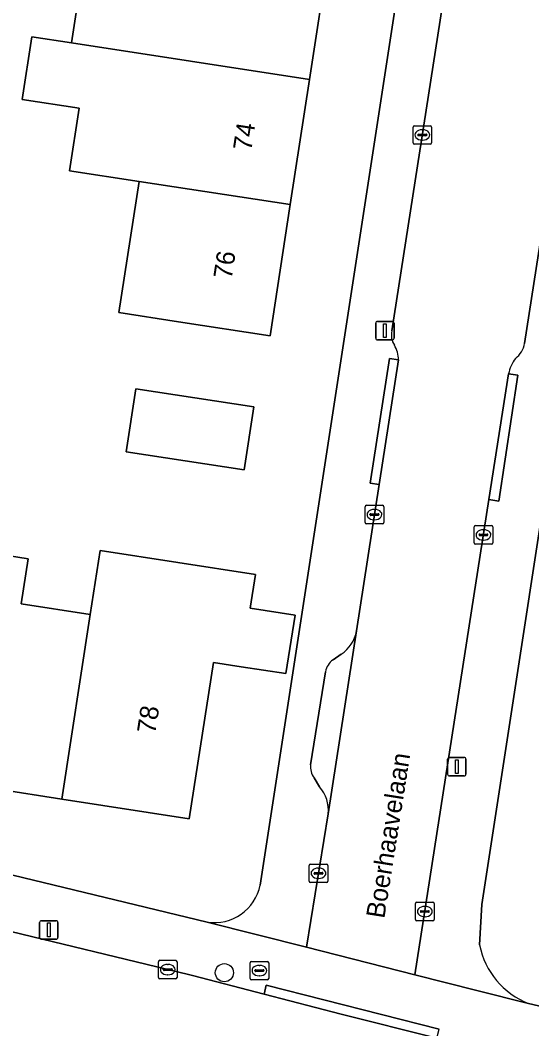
# Model space of a CAD drawing. Extents: x 161483 to 162250, y 379484 to 380833.
# Drawn here: x 161970 to 161997.6, y 380393.9 to 380448.4 of the extents above; entities that cross this region are included whole.
import ezdxf

# ---------------------------------------------------------------- set-up
doc = ezdxf.new("R2010")
doc.units = 0
for name, color, linetype in [('IMGEO_Boom', 7, 'Continuous'), ('IMGEO_Brandkraan', 7, 'Continuous'), ('IMGEO_Erf', 7, 'Continuous'), ('IMGEO_Kolk', 7, 'Continuous'), ('IMGEO_Lichtmast', 7, 'Continuous'), ('IMGEO_Openbare_ruimte_label', 7, 'Continuous'), ('IMGEO_Pand', 7, 'Continuous'), ('IMGEO_Pand_nummerreeks', 7, 'Continuous'), ('IMGEO_Parkeervlak_open', 7, 'Continuous'), ('IMGEO_Rijbaan_lokaal_open', 7, 'Continuous'), ('IMGEO_Voetpad_open', 7, 'Continuous')]:
    doc.layers.add(name, color=color, linetype=linetype)

msp = doc.modelspace()

# ---------------------------------------------------------------- linework, layer by layer
at = {"layer": 'IMGEO_Boom'}
msp.add_circle((161980.989, 380396.97), 0.489, dxfattribs=at)
at = {"layer": 'IMGEO_Brandkraan'}
for p, q in [((161982.38, 380396.657), (161982.38, 380397.509)), ((161982.455, 380397.583), (161983.307, 380397.583)), ((161983.381, 380397.509), (161983.381, 380396.657)), ((161982.639, 380397.077), (161982.639, 380397.089)), ((161983.077, 380397.04), (161982.679, 380397.04)), ((161982.682, 380397.126), (161983.08, 380397.126)), ((161982.868, 380397.363), (161982.893, 380397.363)), ((161983.123, 380397.089), (161983.123, 380397.077)), ((161983.307, 380396.583), (161982.455, 380396.583)), ((161982.891, 380396.803), (161982.866, 380396.803))]:
    msp.add_line(p, q, dxfattribs=at)
for points in [[(161982.38, 380396.657), (161982.38, 380397.509)], [(161982.455, 380397.583), (161983.307, 380397.583)], [(161983.381, 380397.509), (161983.381, 380396.657)], [(161983.307, 380396.583), (161982.455, 380396.583)]]:
    msp.add_lwpolyline(points, dxfattribs=at)
for centre, radius, start, end in [((161982.457, 380397.507), 0.0765, 91.552, 178.448), ((161982.457, 380397.507), 0.0765, 91.552, 178.448), ((161983.305, 380397.507), 0.0765, 1.552, 88.448), ((161983.305, 380397.507), 0.0765, 1.552, 88.448), ((161982.679, 380397.086), 0.0403, 85.8775, 175.7526), ((161982.676, 380397.076), 0.0366, 178.938, 274.7102), ((161983.08, 380397.083), 0.043, 264.8664, 352.4533), ((161983.084, 380397.088), 0.0386, 1.7309, 96.639), ((161982.457, 380396.659), 0.0765, 181.552, 268.448), ((161982.457, 380396.659), 0.0765, 181.552, 268.448), ((161983.305, 380396.659), 0.0765, 271.552, 358.448), ((161983.305, 380396.659), 0.0765, 271.552, 358.448)]:
    msp.add_arc(centre, radius, start, end, dxfattribs=at)
for centre, major_axis, ratio, start_param, end_param in [((161982.867, 380397.083), (-0.387, 0.002), 0.722429, 4.712389, 7.853982), ((161982.892, 380397.083), (-0.39, 0.002), 0.717154, 1.570796, 4.712389)]:
    msp.add_ellipse(centre, major_axis=major_axis, ratio=ratio, start_param=start_param, end_param=end_param, dxfattribs=at)
at = {"layer": 'IMGEO_Erf'}
for points in [[(161982.918, 380401.702), (161997.393, 380495.855)], [(161986.642, 380452.095), (161985.583, 380445.183), (161984.547, 380438.423), (161983.461, 380431.341), (161978.519, 380432.098), (161975.296, 380432.592), (161976.382, 380439.675), (161972.627, 380440.25), (161973.145, 380443.63), (161970.08, 380444.1), (161970.598, 380447.48), (161972.74, 380447.152), (161973.799, 380454.063)], [(162000, 380433.985), (161994.885, 380400.652), (161994.764, 380398.467)], [(161917.857, 380414.284), (161947.471, 380407.585), (161980.058, 380399.699)], [(161997.399, 380395.311), (162000, 380394.69), (162043.415, 380384.478), (162054.712, 380382.262)]]:
    msp.add_lwpolyline(points, dxfattribs=at)
for points in [[(161982.582, 380427.507), (161982.061, 380424.107), (161975.686, 380425.085), (161976.208, 380428.484)], [(161982.661, 380418.463), (161982.379, 380416.643), (161984.801, 380416.269), (161984.313, 380413.109), (161981.889, 380413.483), (161980.406, 380413.712), (161979.096, 380405.273), (161972.21, 380406.342), (161965.323, 380407.412), (161966.09, 380412.353), (161967.248, 380419.805), (161970.406, 380419.315), (161970.028, 380416.881), (161973.754, 380416.302), (161974.29, 380419.761)]]:
    msp.add_lwpolyline(points, close=True, dxfattribs=at)
for centre, radius, start, end in [((161980.445, 380402.189), 2.52, 261.1627, 348.8482), ((161998.934, 380399.271), 4.247, 190.9075, 248.8107)]:
    msp.add_arc(centre, radius, start, end, dxfattribs=at)
at = {"layer": 'IMGEO_Kolk'}
for p, q in [((161991.246, 380442.682), (161992.098, 380442.682)), ((161991.171, 380441.756), (161991.171, 380442.608)), ((161991.43, 380442.176), (161991.43, 380442.188)), ((161991.868, 380442.139), (161991.47, 380442.139)), ((161991.473, 380442.225), (161991.871, 380442.225)), ((161991.659, 380442.462), (161991.684, 380442.462)), ((161991.914, 380442.188), (161991.914, 380442.176)), ((161992.172, 380442.608), (161992.172, 380441.756)), ((161992.098, 380441.682), (161991.246, 380441.682)), ((161991.682, 380441.902), (161991.657, 380441.902)), ((161988.587, 380421.269), (161988.587, 380422.121)), ((161988.662, 380422.195), (161989.514, 380422.195)), ((161989.075, 380421.975), (161989.1, 380421.975)), ((161989.588, 380422.121), (161989.588, 380421.269)), ((161988.846, 380421.689), (161988.846, 380421.701)), ((161989.284, 380421.652), (161988.886, 380421.652)), ((161988.889, 380421.738), (161989.287, 380421.738)), ((161989.098, 380421.415), (161989.073, 380421.415)), ((161989.33, 380421.701), (161989.33, 380421.689)), ((161989.514, 380421.195), (161988.662, 380421.195)), ((161994.469, 380420.173), (161994.469, 380421.025)), ((161994.544, 380421.099), (161995.396, 380421.099)), ((161994.957, 380420.879), (161994.982, 380420.879)), ((161995.47, 380421.025), (161995.47, 380420.173)), ((161994.728, 380420.593), (161994.728, 380420.605)), ((161995.166, 380420.556), (161994.768, 380420.556)), ((161994.771, 380420.642), (161995.169, 380420.642)), ((161994.98, 380420.319), (161994.955, 380420.319)), ((161995.212, 380420.605), (161995.212, 380420.593)), ((161995.396, 380420.099), (161994.544, 380420.099)), ((161985.567, 380401.909), (161985.567, 380402.761)), ((161985.642, 380402.835), (161986.494, 380402.835)), ((161985.826, 380402.329), (161985.826, 380402.341)), ((161985.869, 380402.378), (161986.267, 380402.378)), ((161986.055, 380402.615), (161986.08, 380402.615)), ((161986.31, 380402.341), (161986.31, 380402.329)), ((161986.568, 380402.761), (161986.568, 380401.909)), ((161986.494, 380401.835), (161985.642, 380401.835)), ((161986.264, 380402.292), (161985.866, 380402.292)), ((161986.078, 380402.055), (161986.053, 380402.055)), ((161991.305, 380399.846), (161991.305, 380400.698)), ((161991.38, 380400.772), (161992.232, 380400.772)), ((161992.306, 380400.698), (161992.306, 380399.846)), ((161991.564, 380400.266), (161991.564, 380400.278)), ((161992.002, 380400.229), (161991.604, 380400.229)), ((161991.607, 380400.315), (161992.005, 380400.315)), ((161991.793, 380400.552), (161991.818, 380400.552)), ((161992.048, 380400.278), (161992.048, 380400.266)), ((161992.232, 380399.772), (161991.38, 380399.772)), ((161991.816, 380399.992), (161991.791, 380399.992)), ((161977.434, 380396.712), (161977.434, 380397.564)), ((161977.509, 380397.638), (161978.361, 380397.638)), ((161978.435, 380397.564), (161978.435, 380396.712)), ((161977.693, 380397.132), (161977.693, 380397.144)), ((161978.131, 380397.095), (161977.733, 380397.095)), ((161977.736, 380397.181), (161978.134, 380397.181)), ((161977.922, 380397.418), (161977.947, 380397.418)), ((161978.177, 380397.144), (161978.177, 380397.132)), ((161978.361, 380396.638), (161977.509, 380396.638)), ((161977.945, 380396.858), (161977.92, 380396.858))]:
    msp.add_line(p, q, dxfattribs=at)
for points in [[(161991.246, 380442.682), (161992.098, 380442.682)], [(161991.171, 380441.756), (161991.171, 380442.608)], [(161992.172, 380442.608), (161992.172, 380441.756)], [(161992.098, 380441.682), (161991.246, 380441.682)], [(161988.587, 380421.269), (161988.587, 380422.121)], [(161988.662, 380422.195), (161989.514, 380422.195)], [(161989.588, 380422.121), (161989.588, 380421.269)], [(161989.514, 380421.195), (161988.662, 380421.195)], [(161994.469, 380420.173), (161994.469, 380421.025)], [(161994.544, 380421.099), (161995.396, 380421.099)], [(161995.47, 380421.025), (161995.47, 380420.173)], [(161995.396, 380420.099), (161994.544, 380420.099)], [(161985.567, 380401.909), (161985.567, 380402.761)], [(161985.642, 380402.835), (161986.494, 380402.835)], [(161986.568, 380402.761), (161986.568, 380401.909)], [(161986.494, 380401.835), (161985.642, 380401.835)], [(161991.305, 380399.846), (161991.305, 380400.698)], [(161991.38, 380400.772), (161992.232, 380400.772)], [(161992.306, 380400.698), (161992.306, 380399.846)], [(161992.232, 380399.772), (161991.38, 380399.772)], [(161977.434, 380396.712), (161977.434, 380397.564)], [(161977.509, 380397.638), (161978.361, 380397.638)], [(161978.435, 380397.564), (161978.435, 380396.712)], [(161978.361, 380396.638), (161977.509, 380396.638)]]:
    msp.add_lwpolyline(points, dxfattribs=at)
for centre, radius, start, end in [((161991.248, 380442.606), 0.0765, 91.552, 178.448), ((161991.248, 380442.606), 0.0765, 91.552, 178.448), ((161992.096, 380442.606), 0.0765, 1.552, 88.448), ((161992.096, 380442.606), 0.0765, 1.552, 88.448), ((161991.47, 380442.185), 0.0403, 85.8775, 175.7526), ((161991.467, 380442.175), 0.0366, 178.938, 274.7102), ((161991.871, 380442.182), 0.043, 264.8664, 352.4533), ((161991.875, 380442.187), 0.0386, 1.7309, 96.639), ((161991.248, 380441.758), 0.0765, 181.552, 268.448), ((161991.248, 380441.758), 0.0765, 181.552, 268.448), ((161992.096, 380441.758), 0.0765, 271.552, 358.448), ((161992.096, 380441.758), 0.0765, 271.552, 358.448), ((161988.664, 380422.119), 0.0765, 91.552, 178.448), ((161988.664, 380422.119), 0.0765, 91.552, 178.448), ((161989.512, 380422.119), 0.0765, 1.552, 88.448), ((161989.512, 380422.119), 0.0765, 1.552, 88.448), ((161988.886, 380421.698), 0.0403, 85.8775, 175.7526), ((161988.883, 380421.688), 0.0366, 178.938, 274.7102), ((161989.287, 380421.695), 0.043, 264.8664, 352.4533), ((161989.291, 380421.7), 0.0386, 1.7309, 96.639), ((161988.664, 380421.271), 0.0765, 181.552, 268.448), ((161988.664, 380421.271), 0.0765, 181.552, 268.448), ((161989.512, 380421.271), 0.0765, 271.552, 358.448), ((161989.512, 380421.271), 0.0765, 271.552, 358.448), ((161994.546, 380421.023), 0.0765, 91.552, 178.448), ((161994.546, 380421.023), 0.0765, 91.552, 178.448), ((161995.394, 380421.023), 0.0765, 1.552, 88.448), ((161995.394, 380421.023), 0.0765, 1.552, 88.448), ((161994.768, 380420.602), 0.0403, 85.8775, 175.7526), ((161994.765, 380420.592), 0.0366, 178.938, 274.7102), ((161995.169, 380420.599), 0.043, 264.8664, 352.4533), ((161995.173, 380420.604), 0.0386, 1.7309, 96.639), ((161994.546, 380420.175), 0.0765, 181.552, 268.448), ((161994.546, 380420.175), 0.0765, 181.552, 268.448), ((161995.394, 380420.175), 0.0765, 271.552, 358.448), ((161995.394, 380420.175), 0.0765, 271.552, 358.448), ((161985.644, 380402.759), 0.0765, 91.552, 178.448), ((161985.644, 380402.759), 0.0765, 91.552, 178.448), ((161985.866, 380402.338), 0.0403, 85.8775, 175.7526), ((161986.271, 380402.34), 0.0386, 1.7309, 96.639), ((161986.492, 380402.759), 0.0765, 1.552, 88.448), ((161986.492, 380402.759), 0.0765, 1.552, 88.448), ((161985.644, 380401.911), 0.0765, 181.552, 268.448), ((161985.644, 380401.911), 0.0765, 181.552, 268.448), ((161985.863, 380402.328), 0.0366, 178.938, 274.7102), ((161986.267, 380402.335), 0.043, 264.8664, 352.4533), ((161986.492, 380401.911), 0.0765, 271.552, 358.448), ((161986.492, 380401.911), 0.0765, 271.552, 358.448), ((161991.382, 380400.696), 0.0765, 91.552, 178.448), ((161991.382, 380400.696), 0.0765, 91.552, 178.448), ((161992.23, 380400.696), 0.0765, 1.552, 88.448), ((161992.23, 380400.696), 0.0765, 1.552, 88.448), ((161991.604, 380400.275), 0.0403, 85.8775, 175.7526), ((161991.601, 380400.265), 0.0366, 178.938, 274.7102), ((161992.005, 380400.272), 0.043, 264.8664, 352.4533), ((161992.009, 380400.277), 0.0386, 1.7309, 96.639), ((161991.382, 380399.848), 0.0765, 181.552, 268.448), ((161991.382, 380399.848), 0.0765, 181.552, 268.448), ((161992.23, 380399.848), 0.0765, 271.552, 358.448), ((161992.23, 380399.848), 0.0765, 271.552, 358.448), ((161977.511, 380397.562), 0.0765, 91.552, 178.448), ((161977.511, 380397.562), 0.0765, 91.552, 178.448), ((161978.359, 380397.562), 0.0765, 1.552, 88.448), ((161978.359, 380397.562), 0.0765, 1.552, 88.448), ((161977.733, 380397.141), 0.0403, 85.8775, 175.7526), ((161977.73, 380397.131), 0.0366, 178.938, 274.7102), ((161978.134, 380397.138), 0.043, 264.8664, 352.4533), ((161978.138, 380397.143), 0.0386, 1.7309, 96.639), ((161977.511, 380396.714), 0.0765, 181.552, 268.448), ((161977.511, 380396.714), 0.0765, 181.552, 268.448), ((161978.359, 380396.714), 0.0765, 271.552, 358.448), ((161978.359, 380396.714), 0.0765, 271.552, 358.448)]:
    msp.add_arc(centre, radius, start, end, dxfattribs=at)
for centre, major_axis, ratio, start_param, end_param in [((161991.658, 380442.182), (-0.387, 0.002), 0.722429, 4.712389, 7.853982), ((161991.683, 380442.182), (-0.39, 0.002), 0.717154, 1.570796, 4.712389), ((161989.074, 380421.695), (-0.387, 0.002), 0.722429, 4.712389, 7.853982), ((161989.099, 380421.695), (-0.39, 0.002), 0.717154, 1.570796, 4.712389), ((161994.956, 380420.599), (-0.387, 0.002), 0.722429, 4.712389, 7.853982), ((161994.981, 380420.599), (-0.39, 0.002), 0.717154, 1.570796, 4.712389), ((161986.054, 380402.335), (-0.387, 0.002), 0.722429, 4.712389, 7.853982), ((161986.079, 380402.335), (-0.39, 0.002), 0.717154, 1.570796, 4.712389), ((161991.792, 380400.272), (-0.387, 0.002), 0.722429, 4.712389, 7.853982), ((161991.817, 380400.272), (-0.39, 0.002), 0.717154, 1.570796, 4.712389), ((161977.921, 380397.138), (-0.387, 0.002), 0.722429, 4.712389, 7.853982), ((161977.946, 380397.138), (-0.39, 0.002), 0.717154, 1.570796, 4.712389)]:
    msp.add_ellipse(centre, major_axis=major_axis, ratio=ratio, start_param=start_param, end_param=end_param, dxfattribs=at)
at = {"layer": 'IMGEO_Lichtmast'}
for p, q in [((161989.155, 380431.222), (161989.155, 380432.022)), ((161989.155, 380432.022), (161989.155, 380431.222)), ((161989.255, 380432.122), (161990.045, 380432.122)), ((161990.045, 380432.122), (161989.255, 380432.122)), ((161990.145, 380432.022), (161990.145, 380431.222)), ((161990.145, 380431.222), (161990.145, 380432.022)), ((161990.045, 380431.122), (161989.255, 380431.122)), ((161989.255, 380431.122), (161990.045, 380431.122)), ((161993.034, 380407.692), (161993.034, 380408.492)), ((161993.034, 380408.492), (161993.034, 380407.692)), ((161993.134, 380408.592), (161993.924, 380408.592)), ((161993.924, 380408.592), (161993.134, 380408.592)), ((161994.024, 380408.492), (161994.024, 380407.692)), ((161994.024, 380407.692), (161994.024, 380408.492)), ((161993.924, 380407.592), (161993.134, 380407.592)), ((161993.134, 380407.592), (161993.924, 380407.592)), ((161971.015, 380398.878), (161971.015, 380399.678)), ((161971.015, 380399.678), (161971.015, 380398.878)), ((161971.115, 380399.778), (161971.905, 380399.778)), ((161971.905, 380399.778), (161971.115, 380399.778)), ((161972.005, 380399.678), (161972.005, 380398.878)), ((161972.005, 380398.878), (161972.005, 380399.678)), ((161971.905, 380398.778), (161971.115, 380398.778)), ((161971.115, 380398.778), (161971.905, 380398.778))]:
    msp.add_line(p, q, dxfattribs=at)
for points in [[(161989.575, 380431.997), (161989.725, 380431.997), (161989.725, 380431.247), (161989.575, 380431.247), (161989.575, 380431.997)], [(161993.454, 380408.467), (161993.604, 380408.467), (161993.604, 380407.717), (161993.454, 380407.717), (161993.454, 380408.467)], [(161971.435, 380399.653), (161971.585, 380399.653), (161971.585, 380398.903), (161971.435, 380398.903), (161971.435, 380399.653)]]:
    msp.add_lwpolyline(points, dxfattribs=at)
for centre, start, end in [((161989.255, 380432.022), 90, 180), ((161989.255, 380432.022), 90, 180), ((161990.045, 380432.022), 0, 90), ((161990.045, 380432.022), 360, 90), ((161989.255, 380431.222), 180, 270), ((161989.255, 380431.222), 180, 270), ((161990.045, 380431.222), 270, 0), ((161990.045, 380431.222), 270, 0), ((161993.134, 380408.492), 90, 180), ((161993.134, 380408.492), 90, 180), ((161993.924, 380408.492), 0, 90), ((161993.924, 380408.492), 360, 90), ((161993.134, 380407.692), 180, 270), ((161993.134, 380407.692), 180, 270), ((161993.924, 380407.692), 270, 0), ((161993.924, 380407.692), 270, 0), ((161971.115, 380399.678), 90, 180), ((161971.115, 380399.678), 90, 180), ((161971.905, 380399.678), 0, 90), ((161971.905, 380399.678), 360, 90), ((161971.115, 380398.878), 180, 270), ((161971.115, 380398.878), 180, 270), ((161971.905, 380398.878), 270, 0), ((161971.905, 380398.878), 270, 0)]:
    msp.add_arc(centre, 0.1, start, end, dxfattribs=at)
at = {"layer": 'IMGEO_Pand'}
for points in [[(161972.74, 380447.152), (161985.583, 380445.183), (161986.642, 380452.095), (161975.755, 380453.763), (161973.799, 380454.063)], [(161985.583, 380445.183), (161972.74, 380447.152), (161970.598, 380447.48), (161970.08, 380444.1), (161973.145, 380443.63), (161972.627, 380440.25), (161976.382, 380439.675), (161984.547, 380438.423)], [(161976.382, 380439.675), (161975.296, 380432.592), (161978.519, 380432.098), (161983.461, 380431.341), (161984.547, 380438.423)], [(161982.061, 380424.107), (161982.582, 380427.507), (161976.208, 380428.484), (161975.686, 380425.085)], [(161972.21, 380406.342), (161973.754, 380416.302), (161970.028, 380416.881), (161970.406, 380419.315), (161967.248, 380419.805), (161966.09, 380412.353), (161965.323, 380407.412)], [(161980.406, 380413.712), (161981.889, 380413.483), (161984.313, 380413.109), (161984.801, 380416.269), (161982.379, 380416.643), (161982.661, 380418.463), (161974.29, 380419.761), (161973.754, 380416.302), (161972.21, 380406.342), (161979.096, 380405.273)]]:
    msp.add_lwpolyline(points, close=True, dxfattribs=at)
at = {"layer": 'IMGEO_Parkeervlak_open'}
for points in [[(161986.591, 380405.549), (161988.116, 380415.417)], [(161987.295, 380414.163), (161986.853, 380413.854)], [(161986.44, 380413.214), (161985.644, 380408.19)], [(161985.827, 380407.488), (161986.117, 380406.997)]]:
    msp.add_lwpolyline(points, dxfattribs=at)
for centre, radius, start, end in [((161986.268, 380415.731), 1.875, 303.2273, 350.3468), ((161987.418, 380413.036), 0.994, 124.6427, 169.688), ((161986.6, 380408.064), 0.964, 172.5142, 216.7076), ((161984.752, 380405.748), 1.85, 353.8095, 42.442)]:
    msp.add_arc(centre, radius, start, end, dxfattribs=at)
at = {"layer": 'IMGEO_Rijbaan_lokaal_open'}
for points in [[(162005.978, 380491.592), (162006.784, 380496.829), (162007.271, 380500), (162009.728, 380516.285), (162010.756, 380522.832), (162010.932, 380524.02), (162005.085, 380524.854), (162004.891, 380523.86), (162003.878, 380516.894), (162001.249, 380500), (162000.753, 380496.771), (162000.066, 380492.294), (162000, 380492.002), (161999.789, 380491.531), (161999.389, 380490.794), (161999.112, 380490.027), (161990.029, 380431.608)], [(161997.191, 380430.934), (162000, 380449.079), (162006.268, 380489.565)], [(161990.385, 380430.04), (161989.341, 380423.309), (161988.116, 380415.417), (161986.591, 380405.549), (161985.423, 380398.353), (161991.274, 380396.858), (161995.266, 380422.504), (161996.322, 380429.291)], [(161992.46, 380393.44), (161987.286, 380394.727), (161983.129, 380395.815), (161979.272, 380396.825), (161979.053, 380396.866), (161968.34, 380399.467), (161960.942, 380401.274), (161954.267, 380402.904), (161938.867, 380406.475)]]:
    msp.add_lwpolyline(points, dxfattribs=at)
for centre, radius, start, end in [((161990.973, 380431.379), 0.972, 166.3549, 213.3957), ((161988.728, 380430.013), 1.657, 0.9218, 30.0823), ((161995.872, 380431.187), 1.343, 307.5256, 349.1257), ((161998.358, 380428.887), 2.075, 143.4663, 168.7623)]:
    msp.add_arc(centre, radius, start, end, dxfattribs=at)
at = {"layer": 'IMGEO_Voetpad_open'}
for points in [[(162005.228, 380525.716), (162000.674, 380526.189), (162001.144, 380525.735), (162001.658, 380524.62), (162001.728, 380523.906), (162000, 380512.813), (161998.03, 380500), (161997.539, 380496.804), (161997.393, 380495.855), (161982.918, 380401.702)], [(161990.029, 380431.608), (161999.112, 380490.027), (161999.389, 380490.794), (161999.789, 380491.531), (162000, 380492.002), (162000.066, 380492.294), (161999.572, 380492.37), (162000, 380495.135), (162000.265, 380496.846), (162000.753, 380496.771), (162001.249, 380500), (162003.878, 380516.894), (162004.891, 380523.86), (162005.085, 380524.854)], [(161994.764, 380398.467), (161994.885, 380400.652), (162000, 380433.985), (162009.269, 380494.234)], [(162006.268, 380489.565), (162000, 380449.079), (161997.191, 380430.934)], [(161989.341, 380423.309), (161988.857, 380423.382), (161989.891, 380430.115), (161990.385, 380430.04)], [(161996.322, 380429.291), (161996.816, 380429.217), (161995.799, 380422.424), (161995.266, 380422.504), (161991.274, 380396.858), (161994.606, 380396.016), (161997.399, 380395.311)], [(161988.116, 380415.417), (161989.341, 380423.309)], [(161986.853, 380413.854), (161987.295, 380414.163)], [(161985.644, 380408.19), (161986.44, 380413.214)], [(161918.642, 380411.053), (161919.635, 380410.863), (161925.821, 380409.464), (161925.926, 380409.952), (161936.313, 380407.572), (161936.208, 380407.084), (161938.867, 380406.475), (161954.267, 380402.904), (161954.379, 380403.391), (161961.054, 380401.761), (161960.942, 380401.274), (161968.34, 380399.467), (161979.053, 380396.866), (161979.272, 380396.825), (161983.129, 380395.815), (161983.252, 380396.299), (161992.583, 380393.924)], [(162054.712, 380382.262), (162043.415, 380384.478), (162000, 380394.69), (161997.399, 380395.311), (161994.606, 380396.016), (161991.274, 380396.858), (161985.423, 380398.353), (161980.058, 380399.699), (161947.471, 380407.585)], [(161986.117, 380406.997), (161985.827, 380407.488)], [(161980.058, 380399.699), (161985.423, 380398.353), (161986.591, 380405.549)]]:
    msp.add_lwpolyline(points, dxfattribs=at)
for points in [[(161990.385, 380430.04), (161989.891, 380430.115), (161988.857, 380423.382), (161989.341, 380423.309)], [(161996.322, 380429.291), (161995.266, 380422.504), (161995.799, 380422.424), (161996.816, 380429.217)], [(161992.46, 380393.44), (161992.583, 380393.924), (161983.252, 380396.299), (161983.129, 380395.815), (161987.286, 380394.727)]]:
    msp.add_lwpolyline(points, close=True, dxfattribs=at)
for centre, radius, start, end in [((161990.973, 380431.379), 0.972, 166.3549, 213.3957), ((161988.728, 380430.013), 1.657, 0.9218, 30.0823), ((161995.872, 380431.187), 1.343, 307.5256, 349.1257), ((161998.358, 380428.887), 2.075, 143.4663, 168.7623), ((161986.268, 380415.731), 1.875, 303.2273, 350.3468), ((161987.418, 380413.036), 0.994, 124.6427, 169.688), ((161986.6, 380408.064), 0.964, 172.5142, 216.7076), ((161984.752, 380405.748), 1.85, 353.8095, 42.442), ((161980.445, 380402.189), 2.52, 261.1627, 348.8482), ((161998.934, 380399.271), 4.247, 190.9075, 248.8107)]:
    msp.add_arc(centre, radius, start, end, dxfattribs=at)

# ---------------------------------------------------------------- texts
at = {"layer": 'IMGEO_Openbare_ruimte_label'}
msp.add_text('Boerhaavelaan', height=1, rotation=81.0274, dxfattribs=at).set_placement((161989.618, 380399.861))
at = {"layer": 'IMGEO_Pand_nummerreeks'}
for s, rotation, p in [('74', 81.2855, (161982.437, 380441.292)), ('76', 81.2848, (161981.376, 380434.367)), ('78', 81.1767, (161977.253, 380409.827))]:
    msp.add_text(s, height=1, rotation=rotation, dxfattribs=at).set_placement(p)

doc.saveas('drawing.dxf')
